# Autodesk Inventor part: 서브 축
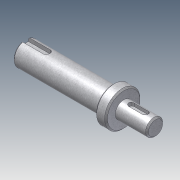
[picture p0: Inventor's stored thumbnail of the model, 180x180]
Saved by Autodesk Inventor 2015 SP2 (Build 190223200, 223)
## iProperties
Company: 한국ATC센터
Created: 2014-10
Part Number: 서브 축
Document SubType Name: Modeling
Designer: KYOUNG IL JANG
Density: 7.85 g/cm^3
Mass: 156.705 g
Surface Area: 57.7178 cm^2
Volume: 19.9624 cm^3
Material: 강철
Appearance: 금속-강(스테인리스, 브러시됨)
Author: KYOUNG IL JANG
Revision Number: 1
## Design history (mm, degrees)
sketch "스케치1"
  geometry: L1 (-16.331, 0)-(-108.831, 0); L2 (-16.331, 0)-(-16.331, -6); L3 (-16.331, -6)-(-38.831, -6); L4 (-38.831, -12.5)-(-46.5, -12.5); L5 (-46.5, -8.5)-(-108.831, -8.5); L6 (-108.831, -8.5)-(-108.831, 0); L7 (-46.5, -8.5)-(-46.5, -12.5); L8 (-38.831, -6)-(-38.831, -12.5); L9 (-46.5, 12.249)-(-46.5, -12.249) reference; L10 (-38.831, -17)-(-38.831, 17) reference; 2 further points
  constraints: 17 end point, 4 perpendicular, 2 collinear, 2 parallel, 1 horizontal, 1 midpoint, 1 point on line
  dimensions: "d1" = 12 diameter of L3 L1; "d2" = 25 diameter of L4 L1; "d3" = 17 diameter of L5 L1; "d4" = 62.33128 distance of L5.start L5.end (derived); "d18" = 22.5 distance of L2.end L3.end; "d20" = 70 distance between parallel lines of L6 L8
revolve "회전1" sketch "스케치1" stored, may be unused: angle "d5" = 90 deg
chamfer "모따기1" distance "d6" = 1; stored, may be unused: second distance "d7" = 2, angle "d8" = 45 deg
node "작업 평면1"
sketch "스케치2"
  geometry: L1 (11.25, 5)-(11.25, -5) reference; L2 (-5.75, -2)-(4.25, -2); L3 (4.25, 2)-(-5.75, 2); A1 r 2 centre (4.25, 0) between (4.25, -2) and (4.25, 2); A2 r 2 centre (-5.75, 0) between (-5.75, 2) and (-5.75, -2); 2 further points
  constraints: 4 end point, 4 point on circle, 4 tangent, 2 centre point, 1 horizontal alignment, 1 midpoint, 1 parallel, 1 perpendicular
  dimensions: "d9" = 4 distance between parallel lines of L2 L3; "d10" = 14 dimension on A1 A2; "d11" = 5 distance edge to line of A1 L1
extrude "돌출1" cut sketch "스케치2" distance "d12" = 2.5; taper "d13" = 0 deg
node "작업 평면2"
sketch "스케치3"
  geometry: L1 (-31.166, -7.5)-(-31.166, 7.5) reference; L2 (-31.166, 2.5)-(-15.666, 2.5); L3 (-15.666, -2.5)-(-31.166, -2.5); A1 r 2.5 centre (-15.666, 0) between (-15.666, -2.5) and (-15.666, 2.5); 2 further points
  constraints: 4 end point, 2 perpendicular, 2 point on circle, 2 point on line, 2 tangent, 1 centre point, 1 horizontal alignment, 1 midpoint
  dimensions: "d14" = 5 distance between parallel lines of L3 L2; "d15" = 18 dimension on A1 L1
extrude "돌출2" cut sketch "스케치3" distance "d16" = 3; taper "d17" = 0 deg
node "솔리드1"
node "참조4"
node "참조5"
